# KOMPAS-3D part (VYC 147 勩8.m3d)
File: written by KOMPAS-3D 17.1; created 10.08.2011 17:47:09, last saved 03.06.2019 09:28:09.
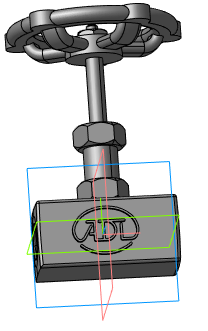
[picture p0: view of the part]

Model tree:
1. Плоскость XY
2. Плоскость ZX
3. Плоскость ZY
4. Ось X
5. Ось Y
6. Ось Z
7. Начало координат
8. Операция без истории:2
